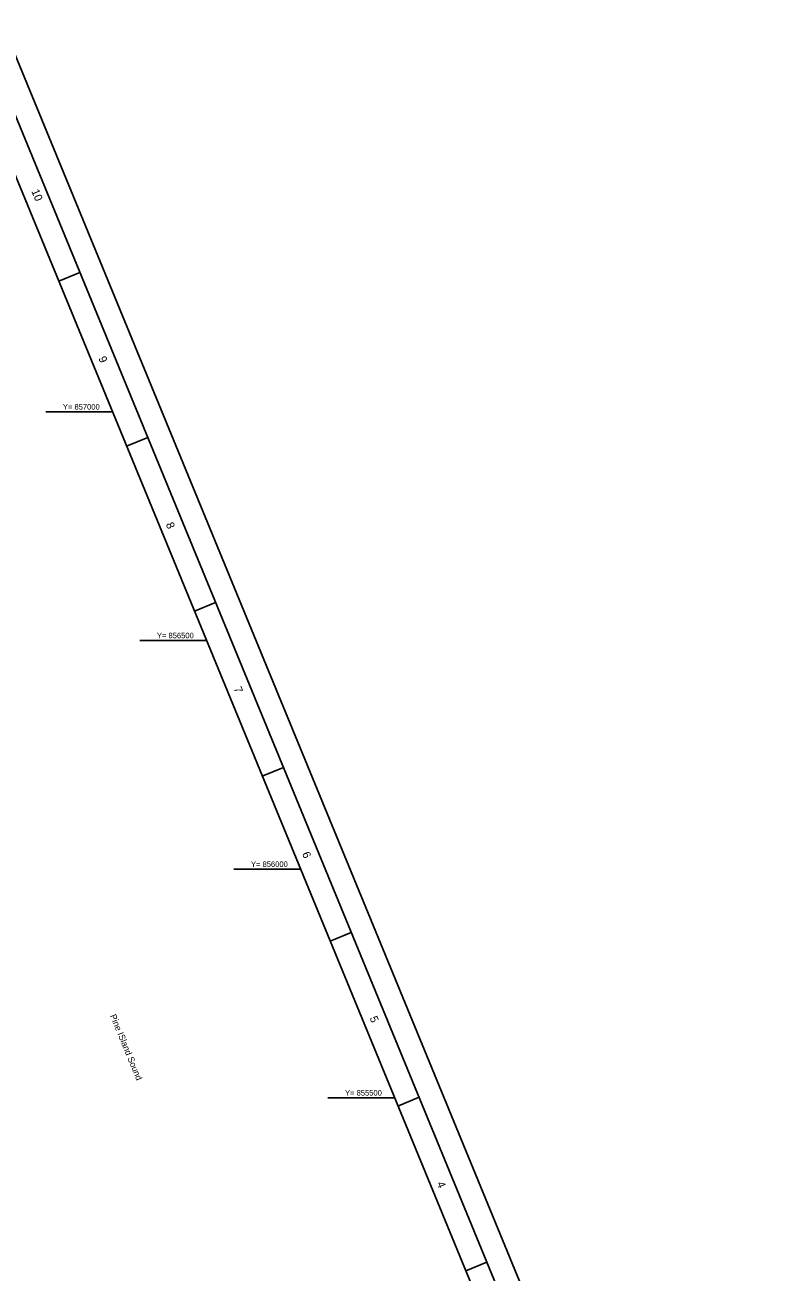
# Model space of a CAD drawing. Extents: x 579601 to 584420, y 852483 to 857846.
# Drawn here: x 582794 to 584420, y 855119 to 857846 of the extents above; entities that cross this region are included whole.
import ezdxf

# ---------------------------------------------------------------- set-up
doc = ezdxf.new("R2010")
doc.units = 0
for name, color, linetype in [('G-ANNO-NPLT', 7, 'Continuous'), ('G-ANNO-TTLB', 7, 'Continuous'), ('V-SITE-WATR', 7, 'Continuous'), ('V-TOPO-COOR-STAT', 7, 'Continuous')]:
    doc.layers.add(name, color=color, linetype=linetype)

msp = doc.modelspace()

# ---------------------------------------------------------------- linework, layer by layer
at = {"layer": 'G-ANNO-NPLT'}
msp.add_lwpolyline([(582745.7, 857846.1), (584419.8, 853777), (581275.5, 852483.4), (579601.4, 856552.5)], close=True, dxfattribs=at)
at = {"layer": 'G-ANNO-TTLB'}
for p, q in [((582914.4, 857304.5), (582868.2, 857285.5)), ((583062.8, 856943.9), (583016.6, 856924.8)), ((583062.8, 856943.9), (583016.6, 856924.8)), ((583211.2, 856583.2), (583164.9, 856564.2)), ((583359.6, 856222.5), (583313.3, 856203.5)), ((583507.9, 855861.9), (583461.7, 855842.8)), ((583656.3, 855501.2), (583610.1, 855482.2)), ((583804.7, 855140.5), (583758.5, 855121.5))]:
    msp.add_line(p, q, dxfattribs=at)
for points in [[(579666.7, 856525.2), (581302.7, 852548.7), (584354.5, 853804.2), (582718.5, 857780.8)], [(584289.2, 853831.4), (582719.8, 857646.2), (579760.5, 856428.7), (581329.9, 852613.9)]]:
    msp.add_lwpolyline(points, close=True, dxfattribs=at)
at = {"layer": 'V-TOPO-COOR-STAT'}
for p, q in [((582839.7, 857000), (582985.6, 857000)), ((583045.4, 856500), (583191.3, 856500)), ((583251.1, 856000), (583397, 856000)), ((583456.8, 855500), (583602.8, 855500))]:
    msp.add_line(p, q, dxfattribs=at)

# ---------------------------------------------------------------- texts
at = {"layer": 'G-ANNO-TTLB'}
for s, p in [('10', (582808, 857482.9)), ('9', (582954.6, 857117.4)), ('8', (583102.1, 856754.4)), ('7', (583250.7, 856395.2)), ('6', (583400.1, 856034)), ('5', (583547.8, 855674.7)), ('4', (583694.7, 855313))]:
    msp.add_text(s, height=17.5, rotation=292.363, dxfattribs=at).set_placement(p)
at = {"layer": 'V-SITE-WATR'}
msp.add_text('Pine ISland Sound', height=13.92, rotation=292.363, dxfattribs=at).set_placement((582980.1, 855679.4))
at = {"layer": 'V-TOPO-COOR-STAT'}
for s, p in [('Y= 857000', (582877.3, 857005)), ('Y= 856500', (583083, 856505)), ('Y= 856000', (583288.7, 856005)), ('Y= 855500', (583494.4, 855505))]:
    msp.add_text(s, height=12, dxfattribs=at).set_placement(p)

doc.saveas('drawing.dxf')
